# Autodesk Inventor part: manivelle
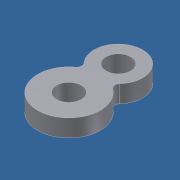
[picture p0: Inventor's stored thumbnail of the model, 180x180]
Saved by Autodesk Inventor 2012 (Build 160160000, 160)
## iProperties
Created: 2011-07
Part Number: manivelle
Document SubType Name: Modeling
Designer: Laur
Density: 7.85 g/cm^3
Material: Acier allié
Mass: 1.5824 g
Surface Area: 3.2003 cm^2
Volume: 0.20158 cm^3
Author: Laur
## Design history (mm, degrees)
sketch "Esquisse1"
  geometry: C1 r 1.77 at (0, 0); C2 r 1.77 at (0, 7.1); A1 r 3.5 centre (0, 7.1) between (2.573, 4.727) and (-2.573, 4.727); A2 r 4.5 centre (0, 0) between (-2.678, 3.616) and (2.678, 3.616); A3 r 0.75 centre (-3.124, 4.219) between (-2.678, 3.616) and (-2.573, 4.727); A4 r 0.75 centre (3.124, 4.219) between (2.573, 4.727) and (2.678, 3.616); 1 further point
  constraints: 8 point on circle, 6 centre point, 4 tangent, 3 coincident
  dimensions: "d0" = 9 diameter of A2; "d1" = 3.54 diameter of C1; "d2" = 3.54 diameter of C2 (= d1); "d3" = 7 diameter of A1; "d4" = 7.1 distance of point (0, 0) C2.centre; "d5" = 0 horizontal distance of C2.centre point (0, 0); "d6" = 1.5 diameter of A3; "d7" = 1.5 diameter of A4 (= d6)
extrude "formes dont Ø3,54" new body sketch "Esquisse1" distance "d8" = 2.5; taper "d9" = 0 deg
sketch "Esquisse2"
  geometry: L1 (0, 0)-(0, 27.555); C1 r 1.77 at (0, 7.1) reference; C2 r 1.77 at (0, 0) reference; A1 r 4.5 centre (0, 0) between (-2.678, 3.616) and (2.678, 3.616) reference; A2 r 0.75 centre (3.124, 4.219) between (2.573, 4.727) and (2.678, 3.616) reference; A3 r 3.5 centre (0, 7.1) between (2.573, 4.727) and (-2.573, 4.727) reference; A4 r 0.75 centre (-3.124, 4.219) between (-2.678, 3.616) and (-2.573, 4.727) reference
  constraints: 2 end point, 1 point on line
sketch "Esquisse3"
  geometry: L1 (0, 0)-(0, 7.1); C1 r 1.77 at (0, 7.1) reference; C2 r 1.77 at (0, 0) reference; A1 r 0.75 centre (-3.124, 4.219) between (-2.678, 3.616) and (-2.573, 4.727) reference; A2 r 4.5 centre (0, 0) between (-2.678, 3.616) and (2.678, 3.616) reference; A3 r 0.75 centre (3.124, 4.219) between (2.573, 4.727) and (2.678, 3.616) reference; A4 r 3.5 centre (0, 7.1) between (2.573, 4.727) and (-2.573, 4.727) reference
  constraints: 2 end point, 1 vertical
node "Solide1"
node "Corps solides"
node "Corps surfaciques"
